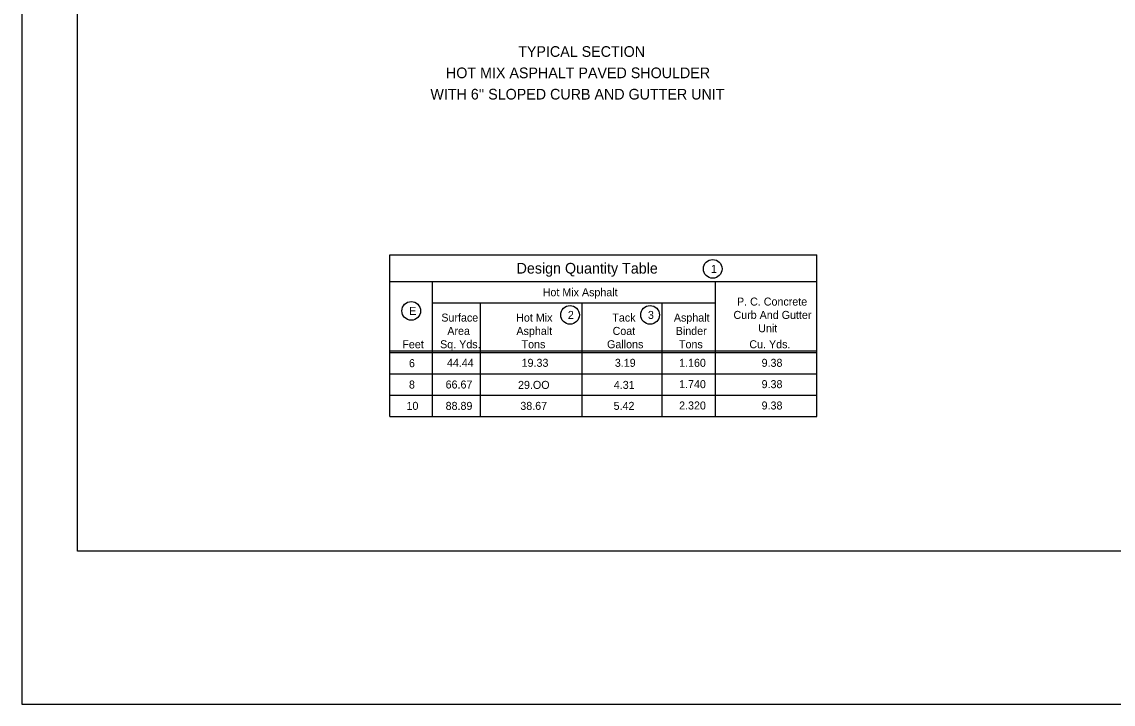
# Model space of a CAD drawing. Extents: x 10133 to 81668, y 2357 to 12713.
# Drawn here: x 10146 to 12191, y 3964 to 5243 of the extents above; entities that cross this region are included whole.
import ezdxf

# ---------------------------------------------------------------- set-up
doc = ezdxf.new("R2010")
doc.units = 0
for name, color, linetype in [('dsnStdBorder', 7, 'Continuous'), ('dsnStdNameDate', 7, 'Continuous'), ('Level 8', 7, 'Continuous'), ('SheetAddendum', 7, 'Continuous'), ('StdLabel', 7, 'Continuous'), ('Text', 7, 'Continuous')]:
    doc.layers.add(name, color=color, linetype=linetype)

msp = doc.modelspace()

# ---------------------------------------------------------------- linework, layer by layer
at = {"layer": 'dsnStdBorder'}
msp.add_lwpolyline([(10250.8, 6261.2), (13385.8, 6261.2), (13385.8, 4251.2), (10250.8, 4251.2)], close=True, dxfattribs=at)
at = {"layer": 'dsnStdNameDate'}
msp.add_circle((10876, 4701.5), 17.5, dxfattribs=at)
at = {"layer": 'SheetAddendum'}
for p, q in [((10836, 4503.5), (10836, 4806.5)), ((10836, 4806.5), (11636, 4806.5)), ((11636, 4503.5), (11636, 4806.5)), ((10836, 4756.5), (11636, 4756.5)), ((10836, 4646.5), (10836, 4756.5)), ((10916, 4503.5), (10916, 4756.5)), ((11446, 4503.5), (11446, 4756.5)), ((10916, 4716.5), (11446, 4716.5)), ((11006, 4503.5), (11006, 4716.5)), ((11196, 4503.5), (11196, 4716.5)), ((11346, 4503.5), (11346, 4716.5)), ((10836, 4626.5), (11636, 4626.5)), ((10836, 4623.5), (11636, 4623.5)), ((10836, 4583.5), (11636, 4583.5)), ((10836, 4543.5), (11636, 4543.5)), ((10836, 4503.5), (11636, 4503.5))]:
    msp.add_line(p, q, dxfattribs=at)
for centre in [(11440.9, 4780.3), (11173.5, 4694), (11323.5, 4694)]:
    msp.add_circle(centre, 17.5, dxfattribs=at)
at = {"layer": 'Text'}
msp.add_lwpolyline([(10146.3, 3964.2), (13490.3, 3964.2), (13490.3, 6548.2), (10146.3, 6548.2)], close=True, dxfattribs=at)

# ---------------------------------------------------------------- texts
at = {"layer": 'dsnStdNameDate'}
for s, height, p in [('Design Quantity Table', 19.999, (11073.4, 4771.5)), ('Hot Mix Asphalt', 15, (11122.3, 4729)), ('P. C. Concrete', 15, (11486.4, 4711.5)), ('E', 15, (10872.1, 4694)), ('Surface', 15, (10932.4, 4681.5)), ('Hot Mix', 15, (11072.6, 4681.5)), ('Tack', 15, (11252.8, 4681.5)), ('Asphalt', 15, (11368.1, 4681.5)), ('Curb And Gutter', 15, (11479.8, 4686.5)), ('Area', 15, (10943.6, 4656.5)), ('Asphalt', 15, (11073.1, 4656.5)), ('Coat', 15, (11253.3, 4656.5)), ('Binder', 15, (11371.6, 4656.5)), ('Unit', 15, (11526.1, 4661.5)), ('Feet', 15, (10859.3, 4631.5)), ('Sq. Yds.', 15, (10930.1, 4631.5)), ('Tons', 15, (11082.7, 4631.5)), ('Gallons', 15, (11242.9, 4631.5)), ('Tons', 15, (11377.7, 4631.5)), ('Cu. Yds.', 15, (11509.6, 4631.5)), ('6', 15, (10871.7, 4596)), ('44.44', 15, (10942.9, 4596.7)), ('19.33', 15, (11082.8, 4596.7)), ('3.19', 15, (11257.5, 4596.7)), ('1.160', 15, (11377.9, 4596.7)), ('9.38', 15, (11532.5, 4596.7)), ('8', 15, (10871.7, 4556)), ('66.67', 15, (10940.4, 4556)), ('29.OO', 15, (11076.1, 4555.3)), ('4.31', 15, (11255.6, 4555.3)), ('1.740', 15, (11377.9, 4556.7)), ('9.38', 15, (11532.5, 4556.7)), ('10', 15, (10867.1, 4516)), ('88.89', 15, (10940.4, 4516)), ('38.67', 15, (11080.4, 4516)), ('5.42', 15, (11255.2, 4516)), ('2.320', 15, (11377.9, 4516.7)), ('9.38', 15, (11532.5, 4516.7))]:
    msp.add_text(s, height=height, dxfattribs=at).set_placement(p)
at = {"layer": 'Level 8'}
for s, p in [('1', (11437.5, 4772.8)), ('2', (11169.5, 4686.5)), ('3', (11319.5, 4686.5))]:
    msp.add_text(s, height=15, dxfattribs=at).set_placement(p)
at = {"layer": 'StdLabel'}
for s, p in [('TYPICAL SECTION', (11076.4, 5177.8)), ('HOT MIX ASPHALT PAVED SHOULDER', (10941.1, 5137.8)), ("WITH 6'' SLOPED CURB AND GUTTER UNIT", (10911.9, 5097.8))]:
    msp.add_text(s, height=20, dxfattribs=at).set_placement(p)

doc.saveas('drawing.dxf')
